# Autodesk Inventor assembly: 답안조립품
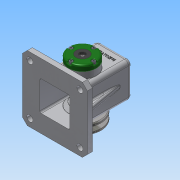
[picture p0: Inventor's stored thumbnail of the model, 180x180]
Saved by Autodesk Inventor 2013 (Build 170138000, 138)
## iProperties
Created: 2016-02
Part Number: 답안조립품
Document SubType Name: Assembly
Designer: Administrator
Author: Administrator
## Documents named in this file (16)
- C:\Users\Administrator\Desktop\460212V1007\답안조립품.iam
- C:\Users\Administrator\Desktop\460212V1007\본체.ipt
- C:\Users\Administrator\Desktop\460212V1007\V벨트풀리.ipt
- C:\Users\Administrator\Desktop\460212V1007\고정핀 1.2 x 10.ipt
- C:\Users\Administrator\Desktop\460212V1007\뒤커버.ipt
- C:\Users\Administrator\Desktop\460212V1007\링크.ipt
- C:\Users\Administrator\Desktop\460212V1007\멈춤나사 M3x8.ipt
- C:\Users\Administrator\Desktop\460212V1007\베어링 12 x 32 x 10.ipt
- C:\Users\Administrator\Desktop\460212V1007\볼트 M4 x 12.ipt
- C:\Users\Administrator\Desktop\460212V1007\부시.ipt
- C:\Users\Administrator\Desktop\460212V1007\슬라이드.ipt
- C:\Users\Administrator\Desktop\460212V1007\앞커버.ipt
- C:\Users\Administrator\Desktop\460212V1007\오일실 12 25 7.ipt
- C:\Users\Administrator\Desktop\460212V1007\키 4 x 4 x 10.ipt
- C:\Users\Administrator\Desktop\460212V1007\편심축.ipt
- C:\Users\Administrator\Desktop\460212V1007\핀 5 x 18.ipt
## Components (11 placed, 4 different names)
1. V벨트풀리:1
2. 고정핀 1.2 x 10:1
3. 핀 5 x 18:1
4. ISO 4762 M4 x 12:2
5. ISO 4762 M4 x 12:3
6. ISO 4762 M4 x 12:4
7. ISO 4762 M4 x 12:5
8. ISO 4762 M4 x 12:1
9. ISO 4762 M4 x 12:6
10. ISO 4762 M4 x 12:7
11. ISO 4762 M4 x 12:8
